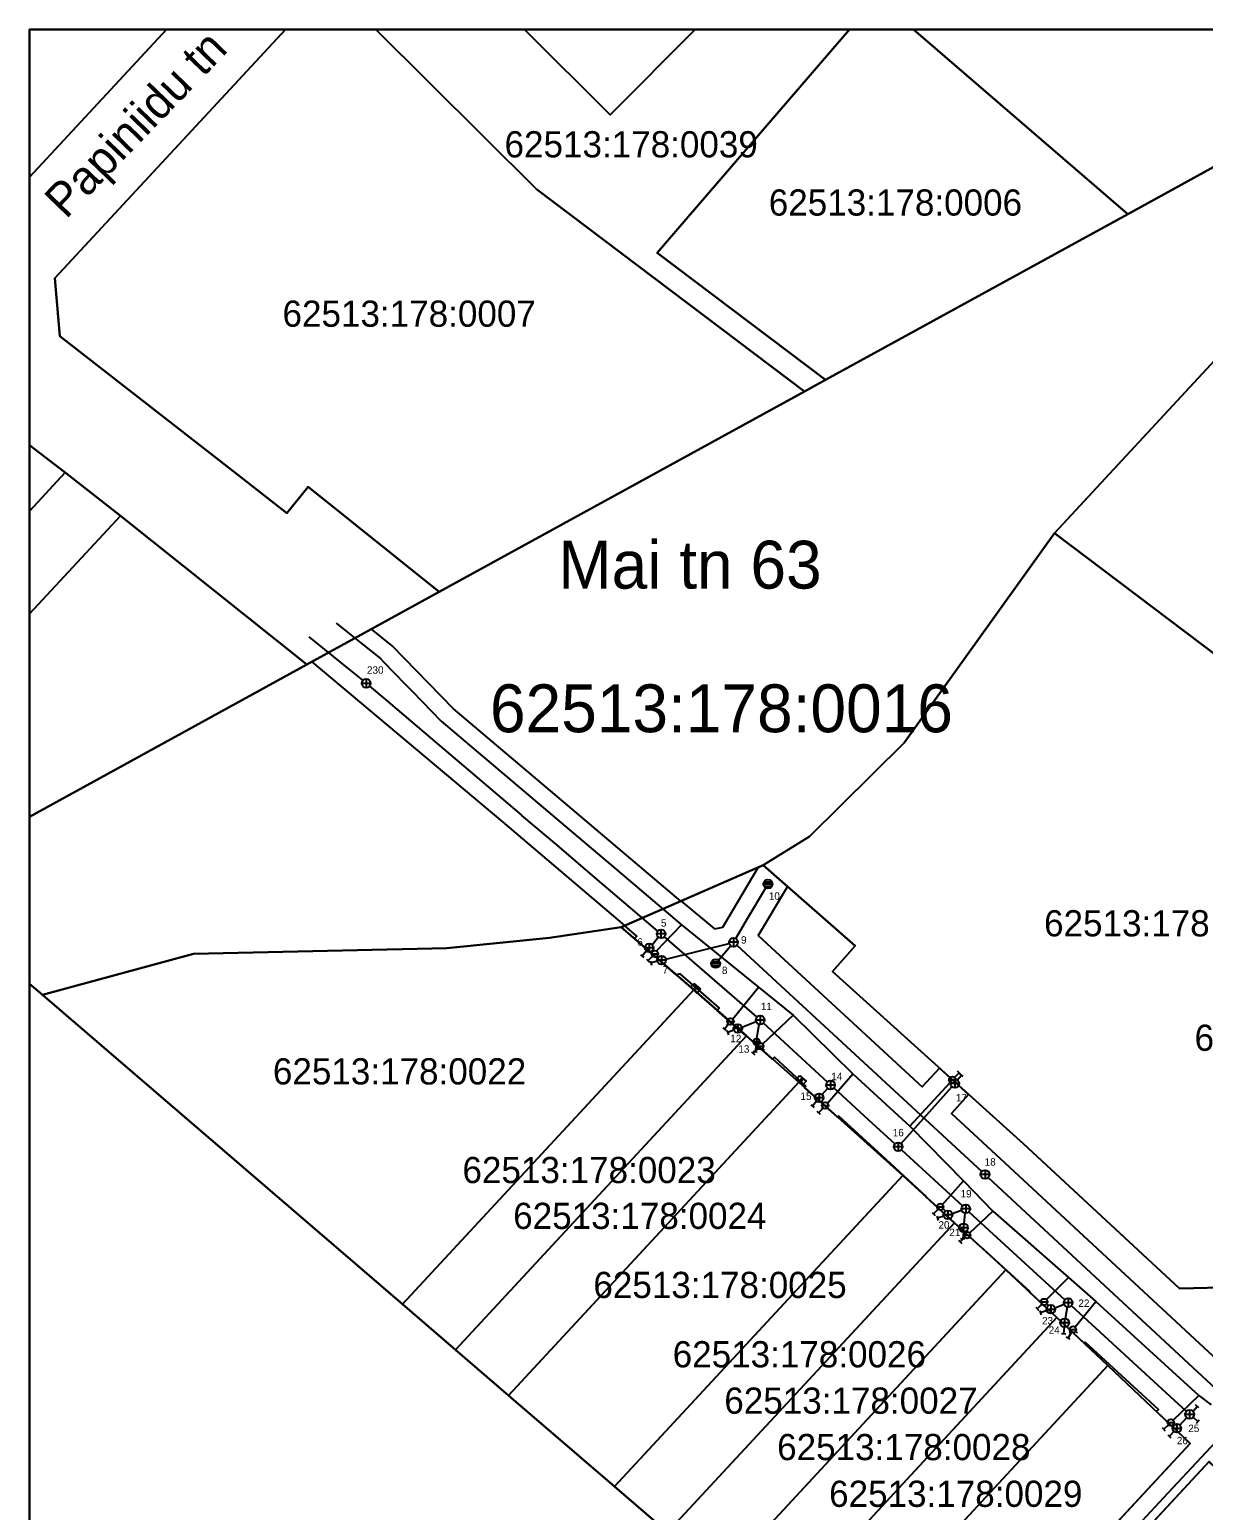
# Model space of a CAD drawing. Extents: x 531722 to 532110, y 6469397 to 6469678.
# Drawn here: x 531722.3 to 531856.7, y 6469508.7 to 6469678.3 of the extents above; entities that cross this region are included whole.
import ezdxf

# ---------------------------------------------------------------- set-up
doc = ezdxf.new("R2010")
doc.units = 0
for name, color, linetype in [('ABIJOONIS', 7, 'Continuous'), ('Default', 7, 'Continuous'), ('ELRAJATISMP', 7, 'Continuous'), ('IKÕ alad', 7, 'Continuous'), ('KAEVUNR_KKAEV', 7, 'Continuous'), ('KAEVUNR_SKKAEV', 7, 'Continuous'), ('KKAEV', 7, 'Continuous'), ('KTRASS', 7, 'Continuous'), ('PIIRIMLEITUD', 7, 'Continuous'), ('SKKAEV', 7, 'Continuous'), ('SKTRASS', 7, 'Continuous'), ('VKAEV', 7, 'Continuous'), ('VORMISTUS', 7, 'Continuous'), ('VTRASS', 7, 'Continuous')]:
    doc.layers.add(name, color=color, linetype=linetype)

msp = doc.modelspace()

# ---------------------------------------------------------------- linework, layer by layer
at = {"layer": 'ELRAJATISMP'}
for p, q in [((531798.65, 6469568.77), (531798.25, 6469568.32)), ((531798.8, 6469568.64), (531798.4, 6469568.19)), ((531810.75, 6469558.23), (531810.36, 6469557.78)), ((531810.91, 6469558.1), (531810.51, 6469557.65))]:
    msp.add_line(p, q, dxfattribs=at)
for points in [[(531798.35, 6469569.04), (531799.1, 6469568.37), (531798.7, 6469567.92), (531797.96, 6469568.59), (531798.35, 6469569.04)], [(531810.45, 6469558.49), (531811.21, 6469557.84), (531810.81, 6469557.39), (531810.06, 6469558.04), (531810.45, 6469558.49)]]:
    msp.add_lwpolyline(points, dxfattribs=at)
at = {"layer": 'IKÕ alad'}
msp.add_line((531790.41, 6469575.65), (531796.85, 6469578.47), dxfattribs=at)
for points in [[(531796.85, 6469578.47), (531783.43, 6469589.83), (531770.81, 6469600.52), (531763.83, 6469607.71), (531761.45, 6469609.61), (531754.62, 6469605.86), (531776.43, 6469587.53), (531790.41, 6469575.65)], [(531823.36, 6469482.02), (531855.16, 6469516.33), (531851.31, 6469519.99), (531851.57, 6469520.23), (531843.15, 6469527.96), (531843.04, 6469527.82), (531839.91, 6469530.76), (531836.77, 6469533.68), (531836.83, 6469533.74), (531831.19, 6469538.9), (531831.16, 6469538.87), (531828.16, 6469541.62), (531824.91, 6469544.59), (531824.95, 6469544.64), (531821.89, 6469547.47), (531820.39, 6469548.85), (531814.97, 6469553.81), (531814.84, 6469553.66), (531811.04, 6469557.08), (531811.13, 6469557.2), (531811.19, 6469557.27), (531807.57, 6469560.6), (531807.33, 6469560.37), (531804.35, 6469563.01), (531801.01, 6469565.94), (531801.25, 6469566.24), (531796.78, 6469570.14), (531796.32, 6469570.02), (531791.55, 6469574.16), (531791.81, 6469574.44), (531790.41, 6469575.65), (531796.87, 6469578.48), (531800.72, 6469575.28), (531801.66, 6469575.49), (531805.7, 6469582.32), (531806.28, 6469582.57), (531809.06, 6469580.13), (531805.71, 6469574.53), (531824.51, 6469557.2), (531826.47, 6469559.32), (531829.8, 6469556.32), (531827.84, 6469554.13), (531833.41, 6469548.99), (531858.3, 6469525.87)], [(531863.88, 6469520.62), (531864.82, 6469519.68), (531863.25, 6469518.11), (531865.6, 6469515.95), (531862.9, 6469513), (531860.34, 6469515.35), (531858.38, 6469513.23), (531857.33, 6469514.25), (531825.63, 6469480.06)]]:
    msp.add_lwpolyline(points, dxfattribs=at)
at = {"layer": 'KKAEV'}
for p, q in [((531760.83, 6469603.9), (531760.83, 6469602.9)), ((531761.33, 6469603.39), (531760.33, 6469603.39)), ((531794.59, 6469575.22), (531794.59, 6469574.22)), ((531793.74, 6469573.1), (531792.74, 6469573.1)), ((531793.24, 6469573.61), (531793.24, 6469572.61)), ((531795.1, 6469574.71), (531794.1, 6469574.71)), ((531806.44, 6469564.83), (531805.44, 6469564.83)), ((531805.94, 6469565.34), (531805.94, 6469564.34)), ((531803.89, 6469563.85), (531802.89, 6469563.85)), ((531803.39, 6469564.36), (531803.39, 6469563.36)), ((531805.9, 6469562.33), (531805.15, 6469562.33)), ((531805.52, 6469562.72), (531805.52, 6469561.96)), ((531814.01, 6469557.91), (531814.01, 6469556.89)), ((531828.22, 6469558.08), (531828.22, 6469557.06)), ((531812.71, 6469556.45), (531812.71, 6469555.43)), ((531814.52, 6469557.39), (531813.52, 6469557.39)), ((531828.72, 6469557.56), (531827.72, 6469557.56)), ((531813.22, 6469555.93), (531812.22, 6469555.93)), ((531822.26, 6469550.32), (531821.26, 6469550.32)), ((531821.75, 6469550.84), (531821.75, 6469549.82)), ((531827.44, 6469543.03), (531827.44, 6469542.01)), ((531829.99, 6469543.2), (531828.99, 6469543.2)), ((531829.48, 6469543.72), (531829.48, 6469542.7)), ((531827.95, 6469542.51), (531826.95, 6469542.51)), ((531829.74, 6469541.04), (531828.74, 6469541.04)), ((531829.24, 6469541.56), (531829.24, 6469540.54)), ((531841.71, 6469532.46), (531840.71, 6469532.46)), ((531841.2, 6469532.98), (531841.2, 6469531.96)), ((531839.73, 6469531.7), (531838.74, 6469531.7)), ((531839.23, 6469532.22), (531839.23, 6469531.2)), ((531840.8, 6469530.68), (531840.8, 6469529.66)), ((531841.31, 6469530.16), (531840.31, 6469530.16)), ((531855.63, 6469519.67), (531854.63, 6469519.67)), ((531855.12, 6469520.19), (531855.12, 6469519.17)), ((531854.15, 6469518.07), (531853.15, 6469518.07)), ((531853.65, 6469518.59), (531853.65, 6469517.57))]:
    msp.add_line(p, q, dxfattribs=at)
for centre, radius in [((531760.83, 6469603.4), 0.5), ((531794.6, 6469574.72), 0.5), ((531793.24, 6469573.11), 0.5), ((531805.94, 6469564.84), 0.5), ((531803.39, 6469563.86), 0.5), ((531805.52, 6469562.34), 0.375), ((531814.01, 6469557.4), 0.5), ((531828.22, 6469557.57), 0.5), ((531812.71, 6469555.94), 0.5), ((531821.75, 6469550.33), 0.5), ((531827.45, 6469542.52), 0.5), ((531829.48, 6469543.21), 0.5), ((531829.24, 6469541.05), 0.5), ((531841.21, 6469532.47), 0.5), ((531839.23, 6469531.71), 0.5), ((531840.81, 6469530.17), 0.5), ((531855.12, 6469519.68), 0.5), ((531853.65, 6469518.08), 0.5)]:
    msp.add_circle(centre, radius, dxfattribs=at)
at = {"layer": 'KTRASS'}
for p, q in [((531792.24, 6469572.31), (531792.63, 6469572)), ((531792.91, 6469572.74), (531792.43, 6469572.15)), ((531802.14, 6469563.63), (531802.31, 6469563.16)), ((531802.93, 6469563.66), (531802.23, 6469563.4)), ((531805.13, 6469561.26), (531805.62, 6469561.19)), ((531805.48, 6469561.97), (531805.38, 6469561.22)), ((531828.52, 6469557.96), (531829.01, 6469558.53)), ((531829.2, 6469558.37), (531828.82, 6469558.69)), ((531811.74, 6469555.12), (531812.13, 6469554.81)), ((531812.41, 6469555.55), (531811.93, 6469554.96)), ((531826.18, 6469542.37), (531826.34, 6469541.89)), ((531826.97, 6469542.37), (531826.26, 6469542.13)), ((531828.9, 6469539.83), (531829.39, 6469539.78)), ((531829.23, 6469540.55), (531829.14, 6469539.81)), ((531837.97, 6469531.55), (531838.13, 6469531.07)), ((531838.76, 6469531.56), (531838.05, 6469531.31)), ((531840.76, 6469529.67), (531840.69, 6469528.92)), ((531840.44, 6469528.95), (531840.94, 6469528.9)), ((531855.49, 6469520.02), (531855.98, 6469520.59)), ((531856.17, 6469520.43), (531855.78, 6469520.75)), ((531855.51, 6469519.36), (531856.06, 6469518.86)), ((531855.89, 6469518.67), (531856.23, 6469519.04)), ((531852.61, 6469517.34), (531852.98, 6469517)), ((531853.3, 6469517.73), (531852.8, 6469517.17))]:
    msp.add_line(p, q, dxfattribs=at)
for points in [[(531754.27, 6469608.71), (531758.86, 6469605.02), (531759.81, 6469604.25), (531760.46, 6469603.73)], [(531761.23, 6469603.09), (531763.09, 6469601.51), (531764.4, 6469600.4), (531778.61, 6469588.31)], [(531778.61, 6469588.31), (531778.63, 6469588.28), (531782.61, 6469584.9), (531787.26, 6469580.94), (531794.2, 6469575.03)], [(531793.58, 6469573.47), (531794.28, 6469574.33)], [(531794.96, 6469574.38), (531805.56, 6469565.16)], [(531803.85, 6469564.04), (531805.47, 6469564.66)], [(531805.58, 6469562.71), (531805.66, 6469563.22), (531805.85, 6469564.34)], [(531806.3, 6469564.5), (531807.21, 6469563.67), (531813.65, 6469557.74)], [(531813.04, 6469556.31), (531813.68, 6469557.03)], [(531814.38, 6469557.06), (531818.33, 6469553.45), (531821.38, 6469550.66)], [(531822.09, 6469550.7), (531827.88, 6469557.19)], [(531822.12, 6469549.99), (531829.12, 6469543.55)], [(531827.92, 6469542.68), (531829.01, 6469543.05)], [(531829.29, 6469541.55), (531829.43, 6469542.71)], [(531829.85, 6469542.87), (531840.84, 6469532.81)], [(531839.7, 6469531.89), (531840.74, 6469532.29)], [(531840.89, 6469530.66), (531841.12, 6469531.98)], [(531841.57, 6469532.13), (531854.76, 6469520.02)], [(531853.99, 6469518.45), (531854.78, 6469519.31)]]:
    msp.add_lwpolyline(points, dxfattribs=at)
at = {"layer": 'PIIRIMLEITUD'}
for points in [[(531722.31, 6469661.37), (531737.98, 6469678.27)], [(531751.61, 6469678.27), (531725.2, 6469649.79), (531725.76, 6469643.16), (531746.28, 6469627.16), (531751.77, 6469622.89), (531754.21, 6469625.92), (531769.21, 6469613.87), (531754.06, 6469605.55), (531732.71, 6469622.59), (531726.38, 6469627.53), (531722.31, 6469630.68)], [(531722.31, 6469588.12), (531754.06, 6469605.55), (531769.21, 6469613.87), (531811.01, 6469636.83), (531813.41, 6469638.15), (531848.03, 6469657.15), (531886.48, 6469678.27)], [(531893.61, 6469678.27), (531899.65, 6469672.42), (531880.45, 6469659.84), (531861.91, 6469644.6), (531839.63, 6469620.61), (531822.45, 6469596.58), (531811.61, 6469585.84), (531806.3, 6469582.57), (531790.04, 6469575.49), (531781.84, 6469574.27), (531770.06, 6469573.06), (531741.07, 6469572.42), (531723.77, 6469567.74), (531722.31, 6469569)], [(531737.98, 6469678.27), (531722.31, 6469661.37)], [(531761.93, 6469678.27), (531780.33, 6469660), (531811.01, 6469636.83), (531769.21, 6469613.87), (531754.21, 6469625.92), (531751.77, 6469622.89), (531746.28, 6469627.16), (531725.76, 6469643.16), (531725.2, 6469649.79), (531751.61, 6469678.27)], [(531816.16, 6469678.27), (531794.15, 6469652.69), (531813.41, 6469638.15), (531811.01, 6469636.83), (531780.33, 6469660), (531761.93, 6469678.27)], [(531798.49, 6469678.27), (531788.79, 6469668.51), (531778.96, 6469678.27)], [(531778.96, 6469678.27), (531788.79, 6469668.51), (531798.49, 6469678.27)], [(531823.49, 6469678.27), (531848.03, 6469657.15), (531813.41, 6469638.15), (531794.15, 6469652.69), (531816.16, 6469678.27)], [(531886.48, 6469678.27), (531848.03, 6469657.15), (531823.49, 6469678.27)], [(531722.31, 6469630.68), (531726.38, 6469627.53), (531722.31, 6469623.13)], [(531722.31, 6469623.13), (531726.38, 6469627.53), (531732.71, 6469622.59), (531722.31, 6469611.37)], [(531722.31, 6469611.37), (531732.71, 6469622.59), (531754.06, 6469605.55), (531722.31, 6469588.12)], [(531823.39, 6469482.03), (531855.18, 6469516.34), (531845.76, 6469525.29), (531839.93, 6469530.77), (531834.07, 6469536.22), (531828.18, 6469541.63), (531822.27, 6469547.02), (531810.36, 6469557.72), (531804.37, 6469563.02), (531798.35, 6469568.28), (531790.04, 6469575.49), (531806.3, 6469582.57), (531816.81, 6469573.34), (531814.22, 6469570.39), (531836.09, 6469550.67), (531853.97, 6469534.09), (531860.32, 6469534.24)], [(531722.31, 6469569), (531723.77, 6469567.74), (531764.98, 6469532.29), (531771.05, 6469527.07), (531777.12, 6469521.84), (531789.25, 6469511.4), (531795.32, 6469506.18), (531801.39, 6469500.96), (531807.46, 6469495.74), (531813.53, 6469490.51), (531823.39, 6469482.03), (531825.66, 6469480.07), (531834.75, 6469472.24), (531840.82, 6469467.02), (531846.89, 6469461.8), (531852.96, 6469456.57), (531859.03, 6469451.36), (531868.13, 6469443.53), (531873.44, 6469438.96), (531843.23, 6469408.7), (531831.64, 6469396.91)], [(531865.97, 6469505.91), (531857.35, 6469514.26), (531825.66, 6469480.07)]]:
    msp.add_lwpolyline(points, dxfattribs=at)
for points in [[(531861.91, 6469644.6), (531898.93, 6469616.64), (531880.79, 6469589.54), (531839.63, 6469620.61)], [(531839.63, 6469620.61), (531880.79, 6469589.54), (531885.26, 6469586.16), (531893.5, 6469569.34), (531888.12, 6469566.7), (531890.65, 6469561.52), (531884.83, 6469557.69), (531877.27, 6469551.51), (531869.22, 6469543.55), (531860.32, 6469534.24), (531853.97, 6469534.09), (531836.09, 6469550.67), (531814.22, 6469570.39), (531816.81, 6469573.34), (531806.3, 6469582.57), (531811.61, 6469585.84), (531822.45, 6469596.58)], [(531790.04, 6469575.49), (531798.35, 6469568.28), (531764.98, 6469532.29), (531723.77, 6469567.74), (531741.07, 6469572.42), (531770.06, 6469573.06), (531781.84, 6469574.27)], [(531798.35, 6469568.28), (531804.37, 6469563.02), (531771.05, 6469527.07), (531764.98, 6469532.29)], [(531804.37, 6469563.02), (531810.36, 6469557.72), (531777.12, 6469521.84), (531771.05, 6469527.07)], [(531810.36, 6469557.72), (531822.27, 6469547.02), (531789.25, 6469511.4), (531777.12, 6469521.84)], [(531822.27, 6469547.02), (531828.18, 6469541.63), (531795.32, 6469506.18), (531789.25, 6469511.4)], [(531828.18, 6469541.63), (531834.07, 6469536.22), (531801.39, 6469500.96), (531795.32, 6469506.18)], [(531834.07, 6469536.22), (531839.93, 6469530.77), (531807.46, 6469495.74), (531801.39, 6469500.96)], [(531839.93, 6469530.77), (531845.76, 6469525.29), (531813.53, 6469490.51), (531807.46, 6469495.74)], [(531845.76, 6469525.29), (531855.18, 6469516.34), (531823.39, 6469482.03), (531813.53, 6469490.51)], [(531857.35, 6469514.26), (531865.97, 6469505.91), (531834.75, 6469472.24), (531825.66, 6469480.07)]]:
    msp.add_lwpolyline(points, close=True, dxfattribs=at)
at = {"layer": 'SKKAEV'}
for p, q in [((531806.34, 6469580.42), (531807.34, 6469580.42)), ((531806.4, 6469580.67), (531807.27, 6469580.67)), ((531806.4, 6469580.17), (531807.27, 6469580.17)), ((531803.39, 6469573.74), (531802.39, 6469573.74)), ((531802.89, 6469574.24), (531802.89, 6469573.24)), ((531795.16, 6469571.69), (531794.16, 6469571.69)), ((531794.66, 6469572.2), (531794.66, 6469571.2)), ((531800.41, 6469571.55), (531801.28, 6469571.55)), ((531800.35, 6469571.3), (531801.35, 6469571.3)), ((531800.41, 6469571.05), (531801.28, 6469571.05)), ((531831.69, 6469547.66), (531831.69, 6469546.66)), ((531832.19, 6469547.16), (531831.19, 6469547.16))]:
    msp.add_line(p, q, dxfattribs=at)
for centre in [(531806.84, 6469580.42), (531802.89, 6469573.74), (531794.66, 6469571.7), (531800.85, 6469571.3), (531831.69, 6469547.16)]:
    msp.add_circle(centre, 0.5, dxfattribs=at)
at = {"layer": 'SKTRASS'}
for p, q in [((531793.39, 6469571.62), (531793.51, 6469571.14)), ((531794.18, 6469571.57), (531793.45, 6469571.38))]:
    msp.add_line(p, q, dxfattribs=at)
for points in [[(531803.15, 6469574.18), (531804.62, 6469576.67), (531806.58, 6469579.99)], [(531795.14, 6469571.82), (531802.41, 6469573.62)], [(531801.17, 6469571.68), (531802.57, 6469573.36)], [(531803.27, 6469573.41), (531831.32, 6469547.5)], [(531832.06, 6469546.82), (531860.8, 6469520.13)], [(531837.8, 6469494.77), (531849.68, 6469507.5), (531852.65, 6469510.67), (531860.82, 6469519.43)]]:
    msp.add_lwpolyline(points, dxfattribs=at)
at = {"layer": 'VKAEV'}
for p, q in [((531793.63, 6469572.16), (531793.45, 6469571.98)), ((531793.52, 6469572.42), (531794.27, 6469572.42)), ((531794.16, 6469572.16), (531794.34, 6469571.98)), ((531802.18, 6469564.68), (531802.93, 6469564.68)), ((531802.29, 6469564.41), (531802.12, 6469564.23)), ((531802.83, 6469564.41), (531803, 6469564.23)), ((531805.69, 6469561.56), (531805.51, 6469561.38)), ((531805.58, 6469561.83), (531806.33, 6469561.83)), ((531806.22, 6469561.56), (531806.4, 6469561.38)), ((531827.57, 6469557.98), (531828.32, 6469557.98)), ((531827.69, 6469557.72), (531827.51, 6469557.53)), ((531828.23, 6469557.75), (531828.44, 6469557.59)), ((531813.13, 6469554.78), (531812.95, 6469554.6)), ((531813.02, 6469555.04), (531813.77, 6469555.04)), ((531813.66, 6469554.78), (531813.83, 6469554.6)), ((531826.32, 6469543.19), (531826.13, 6469543)), ((531826.2, 6469543.45), (531826.95, 6469543.45)), ((531826.86, 6469543.23), (531827.07, 6469543.06)), ((531829.41, 6469539.95), (531829.23, 6469539.76)), ((531829.29, 6469540.21), (531830.04, 6469540.21)), ((531829.95, 6469539.99), (531830.16, 6469539.82)), ((531838.09, 6469532.55), (531838.84, 6469532.55)), ((531838.21, 6469532.29), (531838.03, 6469532.1)), ((531838.75, 6469532.33), (531838.96, 6469532.16)), ((531841.5, 6469529.15), (531841.32, 6469528.97)), ((531841.38, 6469529.41), (531842.13, 6469529.41)), ((531842.04, 6469529.19), (531842.25, 6469529.03)), ((531852.72, 6469518.49), (531852.53, 6469518.31)), ((531852.6, 6469518.75), (531853.35, 6469518.75)), ((531853.25, 6469518.53), (531853.47, 6469518.36))]:
    msp.add_line(p, q, dxfattribs=at)
for centre in [(531793.9, 6469572.42), (531802.56, 6469564.68), (531805.95, 6469561.83), (531827.95, 6469557.98), (531813.39, 6469555.04), (531826.57, 6469543.45), (531829.66, 6469540.21), (531838.46, 6469532.55), (531841.76, 6469529.41), (531852.97, 6469518.75)]:
    msp.add_circle(centre, 0.375, dxfattribs=at)
at = {"layer": 'VORMISTUS'}
msp.add_lwpolyline([(531722.31, 6469396.91), (531927.55, 6469396.91), (531927.55, 6469509.78), (532109.74, 6469509.78), (532109.74, 6469678.27), (531722.31, 6469678.27), (531722.31, 6469396.91)], dxfattribs=at)
msp.add_lwpolyline([(532109.74, 6469396.91), (531722.31, 6469396.91), (531722.31, 6469678.27), (532109.74, 6469678.27)], close=True, dxfattribs=at)
at = {"layer": 'VTRASS'}
for p, q in [((531792.92, 6469571.8), (531793.28, 6469571.45)), ((531793.63, 6469572.16), (531793.1, 6469571.63)), ((531801.68, 6469563.94), (531802.07, 6469563.63)), ((531802.34, 6469564.37), (531801.87, 6469563.79)), ((531804.97, 6469561.21), (531805.33, 6469560.87)), ((531805.67, 6469561.58), (531805.15, 6469561.04)), ((531828.21, 6469558.24), (531828.72, 6469558.8)), ((531828.9, 6469558.63), (531828.53, 6469558.97)), ((531813.15, 6469554.76), (531812.62, 6469554.22)), ((531812.44, 6469554.4), (531812.8, 6469554.05)), ((531825.63, 6469542.8), (531826, 6469542.46)), ((531826.32, 6469543.19), (531825.81, 6469542.63)), ((531828.67, 6469539.62), (531829.02, 6469539.26)), ((531829.39, 6469539.96), (531828.85, 6469539.44)), ((531837.5, 6469531.94), (531837.85, 6469531.58)), ((531838.21, 6469532.29), (531837.68, 6469531.76)), ((531841.6, 6469529.08), (531841.2, 6469528.44)), ((531840.99, 6469528.57), (531841.41, 6469528.31)), ((531851.98, 6469518.18), (531852.31, 6469517.8)), ((531852.7, 6469518.49), (531852.15, 6469517.99))]:
    msp.add_line(p, q, dxfattribs=at)
for points in [[(531757.39, 6469610.28), (531761.74, 6469606.81), (531762.48, 6469606.23), (531762.84, 6469605.86), (531765.31, 6469603.31), (531766.1, 6469602.5), (531769.44, 6469599.06), (531782.14, 6469588.31)], [(531782.14, 6469588.31), (531784.13, 6469586.62), (531789.32, 6469582.23), (531796.95, 6469575.76), (531805.76, 6469568.61), (531809.72, 6469565.4), (531816.57, 6469558.66), (531820.35, 6469555.2), (531823.08, 6469552.7), (531829.23, 6469546.44), (531832.59, 6469542.96), (531841.23, 6469535.35), (531844.37, 6469532.61), (531856.17, 6469521.83), (531857.59, 6469520.77)], [(531794.07, 6469572.75), (531796.95, 6469575.76)], [(531802.8, 6469564.97), (531805.76, 6469568.61)], [(531806.23, 6469562.08), (531809.72, 6469565.4)], [(531813.64, 6469555.33), (531816.57, 6469558.66)], [(531823.08, 6469552.7), (531827.69, 6469557.7)], [(531826.82, 6469543.73), (531829.23, 6469546.44)], [(531829.94, 6469540.47), (531832.59, 6469542.96)], [(531838.73, 6469532.82), (531841.23, 6469535.35)], [(531842, 6469529.71), (531844.37, 6469532.61)], [(531853.24, 6469519.01), (531856.17, 6469521.83)]]:
    msp.add_lwpolyline(points, dxfattribs=at)

# ---------------------------------------------------------------- texts
at = {"layer": 'ABIJOONIS'}
msp.add_text('Papiniidu tn', height=3.8535, rotation=46.0369, dxfattribs=at).set_placement((531726.46, 6469656.48))
for s, p in [('62513:178:0039', (531776.68, 6469663.64)), ('62513:178:0006', (531806.93, 6469656.97)), ('62513:178:0007', (531751.26, 6469644.24)), ('62513:178:0020', (531838.45, 6469574.42)), ('62513:178:0021', (531855.68, 6469561.31)), ('62513:178:0022', (531750.16, 6469557.46)), ('62513:178:0023', (531771.86, 6469546.16)), ('62513:178:0024', (531777.67, 6469540.91)), ('62513:178:0025', (531786.85, 6469533)), ('62513:178:0026', (531795.93, 6469525.06)), ('62513:178:0027', (531801.84, 6469519.75)), ('62513:178:0028', (531807.89, 6469514.43)), ('62513:178:0029', (531813.84, 6469509.08))]:
    msp.add_text(s, height=3, dxfattribs=at).set_placement(p)
at = {"layer": 'Default'}
for s, height, p in [('Mai tn 63', 5.483, (531782.83, 6469614.25)), ('62513:178:0016', 5.4826, (531775.01, 6469597.8))]:
    msp.add_text(s, height=height, dxfattribs=at).set_placement(p)
at = {"layer": 'KAEVUNR_KKAEV'}
for s, p in [('230', (531760.93, 6469604.5)), ('5', (531794.58, 6469575.53)), ('6', (531791.87, 6469573.36)), ('11', (531806.02, 6469565.97)), ('12', (531802.53, 6469562.3)), ('17', (531828.35, 6469555.52)), ('16', (531821.13, 6469551.52)), ('19', (531828.89, 6469544.52)), ('20', (531826.36, 6469540.95)), ('21', (531827.6, 6469540.09)), ('22', (531842.38, 6469531.98)), ('23', (531838.22, 6469529.98)), ('24', (531838.98, 6469528.9)), ('26', (531853.65, 6469516.25)), ('25', (531854.96, 6469517.65))]:
    msp.add_text(s, height=0.85, dxfattribs=at).set_placement(p)
for s, p in [('13', (531803.45, 6469561.1)), ('14', (531814.08, 6469557.95)), ('15', (531810.56, 6469555.69))]:
    msp.add_text(s, height=0.85, rotation=0.0017, dxfattribs=at).set_placement(p)
at = {"layer": 'KAEVUNR_SKKAEV'}
msp.add_text('10', height=0.85, rotation=0.0017, dxfattribs=at).set_placement((531806.94, 6469578.61))
for s, p in [('9', (531803.76, 6469573.59)), ('7', (531794.77, 6469570.15)), ('8', (531801.57, 6469570.11)), ('18', (531831.65, 6469548.16))]:
    msp.add_text(s, height=0.85, dxfattribs=at).set_placement(p)

doc.saveas('drawing.dxf')
